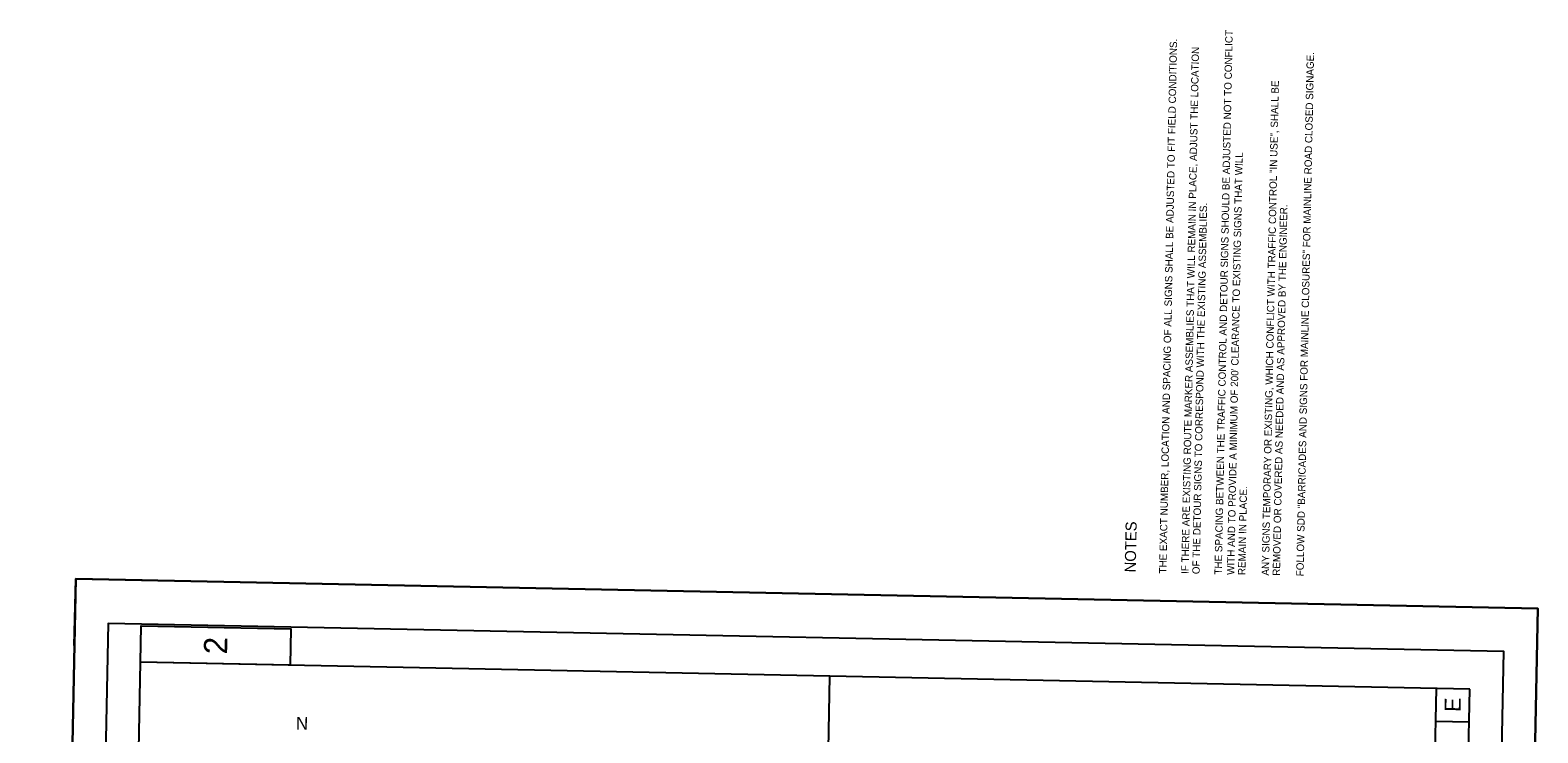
# Model space of a CAD drawing. Extents: x 2191881 to 2513407, y 347956 to 627029.
# Drawn here: x 2411346 to 2513407, y 579445 to 627029 of the extents above; entities that cross this region are included whole.
import ezdxf

# ---------------------------------------------------------------- set-up
doc = ezdxf.new("R2010")
doc.units = 0
for name, color, linetype in [('CA-TEXT', 7, 'Continuous'), ('Level 52', 7, 'Continuous'), ('P_MISC', 7, 'Continuous'), ('P_RDWY_Text', 7, 'Continuous'), ('PLT_Sheet_Border', 7, 'Continuous')]:
    doc.layers.add(name, color=color, linetype=linetype)

msp = doc.modelspace()

# ---------------------------------------------------------------- linework, layer by layer
at = {"layer": 'Level 52'}
for p, q in [((2414336, 585371), (2414427, 589870)), ((2418926, 589779), (2414427, 589870)), ((2513407, 587876), (2508908, 587967)), ((2513316, 583377), (2513407, 587876)), ((2415960, 442501), (2418814, 584223)), ((2508796, 582410), (2418814, 584223)), ((2503692, 440734), (2506546, 582456)), ((2505942, 440689), (2508796, 582410)), ((2508750, 580161), (2506501, 580206))]:
    msp.add_line(p, q, dxfattribs=at)
msp.add_lwpolyline([(2418814, 584223), (2418864, 586697), (2428987, 586493), (2428937, 584019)], close=True, dxfattribs=at)
at = {"layer": 'P_RDWY_Text'}
msp.add_line((2465212, 569646), (2465487, 583283), dxfattribs=at)
msp.add_lwpolyline([(2411346, 436901), (2414427, 589870), (2513407, 587876), (2510326, 434907)], close=True, dxfattribs=at)
at = {"layer": 'PLT_Sheet_Border'}
for points in [[(2510326, 434907), (2513407, 587876), (2414427, 589870), (2411346, 436901)], [(2508098, 436032), (2511097, 584952), (2416617, 586855), (2413617, 437935)]]:
    msp.add_lwpolyline(points, close=True, dxfattribs=at)

# ---------------------------------------------------------------- texts
at = {"layer": 'CA-TEXT'}
for s, height, rotation, p in [('THE SPACING BETWEEN THE TRAFFIC CONTROL AND DETOUR SIGNS SHOULD BE ADJUSTED NOT TO CONFLICT', 500, 88.84622, (2492012, 590154)), ('THE EXACT NUMBER, LOCATION AND SPACING OF ALL SIGNS SHALL BE ADJUSTED TO FIT FIELD CONDITIONS.', 500, 88.84622, (2488263, 590229)), ('IF THERE ARE EXISTING ROUTE MARKER ASSEMBLIES THAT WILL REMAIN IN PLACE, ADJUST THE LOCATION ', 500, 88.84622, (2489762, 590199)), ('FOLLOW SDD "BARRICADES AND SIGNS FOR MAINLINE CLOSURES" FOR MAINLINE ROAD CLOSED SIGNAGE.', 500, 88.84622, (2497546, 590042)), ('ANY SIGNS TEMPORARY OR EXISTING, WHICH CONFLICT WITH TRAFFIC CONTROL "IN USE", SHALL BE', 500, 88.84622, (2495202, 590090)), ("WITH AND TO PROVIDE A MINIMUM OF 200' CLEARANCE TO EXISTING SIGNS THAT WILL", 500, 88.84622, (2492857, 590137)), ('OF THE DETOUR SIGNS TO CORRESPOND WITH THE EXISTING ASSEMBLIES. ', 500, 88.84622, (2490512, 590184)), ('REMOVED OR COVERED AS NEEDED AND AS APPROVED BY THE ENGINEER.', 500, 88.84622, (2495951, 590074)), ('REMAIN IN PLACE.', 500, 88.84622, (2493607, 590122)), ('NOTES', 750, 88.84682, (2486185, 590302))]:
    msp.add_text(s, height=height, rotation=rotation, dxfattribs=at).set_placement(p)
at = {"layer": 'Level 52'}
for s, height, p in [('2', 1575, (2424676, 584753)), ('E', 1080, (2508171, 580856))]:
    msp.add_text(s, height=height, rotation=88.84622, dxfattribs=at).set_placement(p)
at = {"layer": 'P_MISC'}
msp.add_text('N', height=857, rotation=358.84622, dxfattribs=at).set_placement((2429332, 579666))

doc.saveas('drawing.dxf')
